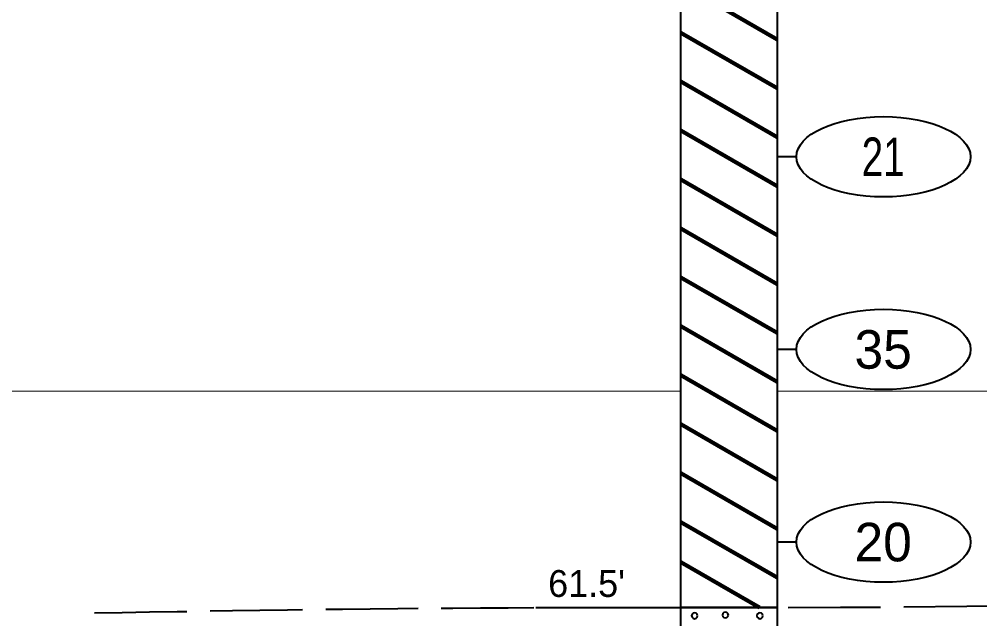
# Model space of a CAD drawing. Extents: x -582 to 653, y -817 to -3.
# Drawn here: x -42.64 to -17.71, y -251.38 to -235.82 of the extents above; entities that cross this region are included whole.
import ezdxf
from ezdxf.enums import TextEntityAlignment as Align

# ---------------------------------------------------------------- set-up
doc = ezdxf.new("R2010")
doc.units = 0
doc.header["$LTSCALE"] = 0.4
doc.linetypes.add('LONG_DASHED', pattern=[7.5, 6, -1.5])
for name, color, linetype, lineweight in [('26', 7, 'LONG_DASHED', 40), ('27', 7, 'Continuous', 40), ('7', 7, 'Continuous', 13)]:
    doc.layers.add(name, color=color, linetype=linetype, lineweight=lineweight)

msp = doc.modelspace()

# ---------------------------------------------------------------- linework, layer by layer
at = {"layer": '26'}
msp.add_spline([(-40.6865, -251.2294), (-29.2387, -251.0929), (-25.4713, -251.0929), (-22.9713, -251.0929), (3.2787, -250.4771)], degree=3, dxfattribs=at)
at = {"layer": '27', "lineweight": 158}
for p, q in [((-25.4713, -234.9029), (-22.9713, -236.3463)), ((-25.4713, -236.1729), (-22.9713, -237.6163)), ((-25.4713, -237.4429), (-22.9713, -238.8863)), ((-25.4713, -238.7129), (-22.9713, -240.1563)), ((-25.4713, -239.9829), (-22.9713, -241.4263)), ((-25.4713, -241.2529), (-22.9713, -242.6963)), ((-25.4713, -242.5229), (-22.9713, -243.9663)), ((-25.4713, -243.7929), (-22.9713, -245.2363)), ((-25.4713, -245.0629), (-22.9713, -246.5063)), ((-25.4713, -246.3329), (-22.9713, -247.7763)), ((-25.4713, -247.6029), (-22.9713, -249.0463)), ((-25.4713, -248.8729), (-22.9713, -250.3163)), ((-25.4713, -249.9126), (-23.4271, -251.0929))]:
    msp.add_line(p, q, dxfattribs=at)
at = {"layer": '27'}
for p, q in [((-22.4714, -239.3929), (-22.9714, -239.3929)), ((-22.4714, -244.3929), (-22.9714, -244.3929)), ((-22.4714, -249.3929), (-22.9714, -249.3929)), ((-29.2387, -251.0929), (-25.4713, -251.0929))]:
    msp.add_line(p, q, dxfattribs=at)
for points in [[(-25.4713, -231.0929), (-22.9713, -231.0929), (-22.9713, -251.0929), (-25.4713, -251.0929)], [(-25.4713, -251.0929), (-22.9713, -251.0929), (-22.9713, -259.3929), (-25.4713, -259.3929)], [(-25.0394, -251.3055), (-25.0496, -251.2674), (-25.0775, -251.2396), (-25.1156, -251.2293), (-25.1537, -251.2396), (-25.1816, -251.2674), (-25.1918, -251.3055), (-25.1816, -251.3436), (-25.1537, -251.3715), (-25.1156, -251.3817), (-25.0775, -251.3715), (-25.0496, -251.3436)], [(-24.2384, -251.286), (-24.2487, -251.2479), (-24.2765, -251.22), (-24.3146, -251.2098), (-24.3527, -251.22), (-24.3806, -251.2479), (-24.3908, -251.286), (-24.3806, -251.3241), (-24.3527, -251.3519), (-24.3146, -251.3622), (-24.2765, -251.3519), (-24.2487, -251.3241)], [(-23.3448, -251.3056), (-23.355, -251.2675), (-23.3829, -251.2396), (-23.421, -251.2294), (-23.4591, -251.2396), (-23.487, -251.2675), (-23.4972, -251.3056), (-23.487, -251.3437), (-23.4591, -251.3716), (-23.421, -251.3818), (-23.3829, -251.3716), (-23.355, -251.3437)]]:
    msp.add_lwpolyline(points, close=True, dxfattribs=at)
for centre in [(-20.214, -239.3929), (-20.214, -244.3929), (-20.214, -249.3929)]:
    msp.add_ellipse(centre, major_axis=(2.2574, 0), ratio=0.461538, dxfattribs=at)
at = {"layer": '7'}
for p, q in [((-62.9147, -245.4729), (-25.4713, -245.4729)), ((-22.9713, -245.4729), (28.379, -245.4729))]:
    msp.add_line(p, q, dxfattribs=at)

# ---------------------------------------------------------------- texts
at = {"layer": '27', "width": 0.75}
msp.add_text('21', height=1, dxfattribs=at).set_placement((-20.2213, -239.8929), align=Align.CENTER)
at = {"layer": '27'}
for s, p in [('35', (-20.2214, -244.8929)), ('20', (-20.2213, -249.8929))]:
    msp.add_text(s, height=1, dxfattribs=at).set_placement(p, align=Align.CENTER)
msp.add_text("61.5'", height=0.6976, dxfattribs=at).set_placement((-28.9146, -250.8165))

doc.saveas('drawing.dxf')
